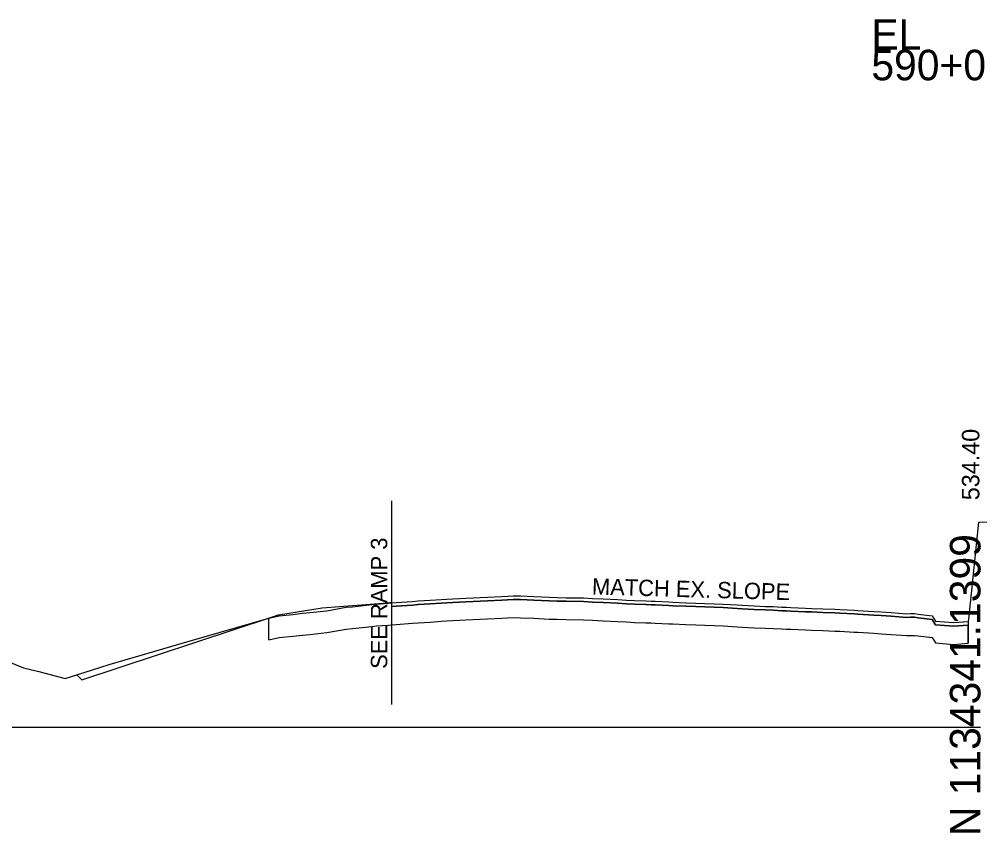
# Model space of a CAD drawing. Extents: x -201 to 2007062, y -213 to 1139737.
# Drawn here: x 1161.9 to 1249.9, y 3990.3 to 4064.9 of the extents above; entities that cross this region are included whole.
import ezdxf

# ---------------------------------------------------------------- set-up
doc = ezdxf.new("R2010")
doc.units = 0
for name, color, linetype in [('RD_DTM_Design_FG', 7, 'Continuous'), ('RD_GPK_XS_Cell', 7, 'Continuous'), ('RD_XS_ExGround', 7, 'Continuous'), ('RD_XS_ExPaveRet', 7, 'Continuous'), ('RD_XS_PaveOvlay', 7, 'Continuous'), ('RD_XS_SideStreet', 7, 'Continuous'), ('RD_XS_TX_Elev_EX', 7, 'Continuous'), ('RD_XS_TX_Slope', 7, 'Continuous')]:
    doc.layers.add(name, color=color, linetype=linetype)

msp = doc.modelspace()

# ---------------------------------------------------------------- linework, layer by layer
at = {"layer": 'RD_DTM_Design_FG'}
msp.add_lwpolyline([(1167.175, 4004.78), (1167.636, 4004.319), (1185.029, 4010.089), (1185.65, 4010.295), (1189.653, 4010.93), (1195.658, 4011.402), (1195.828, 4011.409), (1196, 4011.416)], dxfattribs=at)
at = {"layer": 'RD_GPK_XS_Cell'}
msp.add_line((1000, 4000), (1250, 4000), dxfattribs=at)
at = {"layer": 'RD_XS_ExGround'}
msp.add_lwpolyline([(1141.212, 4014.029), (1162.282, 4005.435), (1163.673, 4005.085), (1166.114, 4004.438), (1168.61, 4005.245), (1170.121, 4005.742), (1177.268, 4007.819), (1184.759, 4009.984), (1185.728, 4010.204), (1186.963, 4010.336), (1187.85, 4010.431), (1188.53, 4010.498), (1190.097, 4010.669), (1191.874, 4010.985), (1192.441, 4011.038), (1194.214, 4011.225), (1194.653, 4011.275), (1195.733, 4011.357), (1196.448, 4011.408), (1197.932, 4011.52), (1198.457, 4011.56), (1199.557, 4011.633), (1200.579, 4011.7), (1201.066, 4011.732), (1202.84, 4011.825), (1204.822, 4011.912), (1206.123, 4011.981), (1207.181, 4012.032), (1207.825, 4012.018), (1209.065, 4011.97), (1210.469, 4011.906), (1211.186, 4011.883), (1212.036, 4011.864), (1213.603, 4011.84), (1214.439, 4011.797), (1215.429, 4011.747), (1216.737, 4011.692), (1217.55, 4011.638), (1218.304, 4011.594), (1219.329, 4011.561), (1219.823, 4011.544), (1220.182, 4011.533), (1221.438, 4011.477), (1221.793, 4011.457), (1223.006, 4011.403), (1223.915, 4011.374), (1226.432, 4011.281), (1227.707, 4011.204), (1228.158, 4011.171), (1229.274, 4011.111), (1230.279, 4011.069), (1230.991, 4011.04), (1231.788, 4010.992), (1232.186, 4010.984), (1232.61, 4010.964), (1233.975, 4010.91), (1234.522, 4010.885), (1235.542, 4010.839), (1236.644, 4010.804), (1237.109, 4010.784), (1238.426, 4010.713), (1238.765, 4010.695), (1240.243, 4010.606), (1240.886, 4010.559), (1241.811, 4010.5), (1243.209, 4010.394), (1243.596, 4010.405), (1243.947, 4010.4), (1244.298, 4010.355), (1245.59, 4010.203), (1245.875, 4009.714), (1247.518, 4009.575), (1248.91, 4009.685), (1248.959, 4010.155), (1249.867, 4018.796), (1250.638, 4018.815)], dxfattribs=at)
at = {"layer": 'RD_XS_ExPaveRet'}
for p, q in [((1196, 4011.043), (1196, 4009.376)), ((1184.758, 4007.984), (1184.758, 4009.984)), ((1202.84, 4009.825), (1204.822, 4009.912)), ((1202.84, 4009.825), (1204.822, 4009.912)), ((1204.822, 4009.912), (1206.123, 4009.981)), ((1204.822, 4009.912), (1206.123, 4009.981)), ((1206.123, 4009.981), (1207.181, 4010.032)), ((1206.123, 4009.981), (1207.181, 4010.032)), ((1207.181, 4010.032), (1207.825, 4010.018)), ((1207.181, 4010.032), (1207.825, 4010.018)), ((1207.825, 4010.018), (1209.065, 4009.97)), ((1207.825, 4010.018), (1209.065, 4009.97)), ((1209.065, 4009.97), (1210.469, 4009.906)), ((1209.065, 4009.97), (1210.469, 4009.906)), ((1210.469, 4009.906), (1211.186, 4009.883)), ((1210.469, 4009.906), (1211.186, 4009.883)), ((1211.186, 4009.883), (1212.036, 4009.864)), ((1211.186, 4009.883), (1212.036, 4009.864)), ((1212.036, 4009.864), (1213.603, 4009.84)), ((1212.036, 4009.864), (1213.603, 4009.84)), ((1190.097, 4008.669), (1191.874, 4008.985)), ((1191.874, 4008.985), (1192.441, 4009.038)), ((1192.441, 4009.038), (1194.214, 4009.225)), ((1194.214, 4009.225), (1194.653, 4009.275)), ((1194.653, 4009.275), (1195.733, 4009.357)), ((1195.733, 4009.357), (1196.448, 4009.408)), ((1196, 4009.376), (1196.448, 4009.408)), ((1196.448, 4009.408), (1197.932, 4009.52)), ((1196.448, 4009.408), (1197.932, 4009.52)), ((1197.932, 4009.52), (1198.457, 4009.56)), ((1197.932, 4009.52), (1198.457, 4009.56)), ((1198.457, 4009.56), (1199.557, 4009.633)), ((1198.457, 4009.56), (1199.557, 4009.633)), ((1199.557, 4009.633), (1200.579, 4009.7)), ((1199.557, 4009.633), (1200.579, 4009.7)), ((1200.579, 4009.7), (1201.066, 4009.732)), ((1200.579, 4009.7), (1201.066, 4009.732)), ((1201.066, 4009.732), (1202.84, 4009.825)), ((1201.066, 4009.732), (1202.84, 4009.825)), ((1213.603, 4009.84), (1214.439, 4009.797)), ((1213.603, 4009.84), (1214.439, 4009.797)), ((1214.439, 4009.797), (1215.429, 4009.747)), ((1214.439, 4009.797), (1215.429, 4009.747)), ((1215.429, 4009.747), (1216.737, 4009.692)), ((1215.429, 4009.747), (1216.737, 4009.692)), ((1216.737, 4009.692), (1217.55, 4009.638)), ((1216.737, 4009.692), (1217.55, 4009.638)), ((1217.55, 4009.638), (1218.304, 4009.594)), ((1217.55, 4009.638), (1218.304, 4009.594)), ((1218.304, 4009.594), (1219.329, 4009.561)), ((1218.304, 4009.594), (1219.329, 4009.561)), ((1219.329, 4009.561), (1219.823, 4009.544)), ((1219.329, 4009.561), (1219.823, 4009.544)), ((1219.823, 4009.544), (1220.182, 4009.533)), ((1219.823, 4009.544), (1220.182, 4009.533)), ((1220.182, 4009.533), (1221.438, 4009.477)), ((1220.182, 4009.533), (1221.438, 4009.477)), ((1221.438, 4009.477), (1221.793, 4009.457)), ((1221.438, 4009.477), (1221.793, 4009.457)), ((1221.793, 4009.457), (1223.006, 4009.403)), ((1221.793, 4009.457), (1223.006, 4009.403)), ((1223.006, 4009.403), (1223.915, 4009.374)), ((1223.006, 4009.403), (1223.915, 4009.374)), ((1223.915, 4009.374), (1226.432, 4009.281)), ((1223.915, 4009.374), (1226.432, 4009.281)), ((1226.432, 4009.281), (1227.707, 4009.204)), ((1226.432, 4009.281), (1227.707, 4009.204)), ((1227.707, 4009.204), (1228.158, 4009.171)), ((1227.707, 4009.204), (1228.158, 4009.171)), ((1228.158, 4009.171), (1229.274, 4009.111)), ((1228.158, 4009.171), (1229.274, 4009.111)), ((1229.274, 4009.111), (1230.279, 4009.069)), ((1229.274, 4009.111), (1230.279, 4009.069)), ((1230.279, 4009.069), (1230.991, 4009.04)), ((1230.279, 4009.069), (1230.991, 4009.04)), ((1230.991, 4009.04), (1231.788, 4008.992)), ((1230.991, 4009.04), (1231.788, 4008.992)), ((1231.788, 4008.992), (1232.186, 4008.984)), ((1231.788, 4008.992), (1232.186, 4008.984)), ((1232.186, 4008.984), (1232.61, 4008.964)), ((1232.186, 4008.984), (1232.61, 4008.964)), ((1248.885, 4009.683), (1248.885, 4007.683)), ((1248.885, 4007.683), (1248.885, 4009.35)), ((1184.759, 4007.984), (1185.728, 4008.204)), ((1185.728, 4008.204), (1186.963, 4008.336)), ((1186.963, 4008.336), (1187.85, 4008.431)), ((1187.85, 4008.431), (1188.53, 4008.498)), ((1188.53, 4008.498), (1190.097, 4008.669)), ((1232.61, 4008.964), (1233.975, 4008.91)), ((1232.61, 4008.964), (1233.975, 4008.91)), ((1233.975, 4008.91), (1234.522, 4008.885)), ((1233.975, 4008.91), (1234.522, 4008.885)), ((1234.522, 4008.885), (1235.542, 4008.839)), ((1234.522, 4008.885), (1235.542, 4008.839)), ((1235.542, 4008.839), (1236.644, 4008.804)), ((1235.542, 4008.839), (1236.644, 4008.804)), ((1236.644, 4008.804), (1237.109, 4008.784)), ((1236.644, 4008.804), (1237.109, 4008.784)), ((1237.109, 4008.784), (1238.426, 4008.713)), ((1237.109, 4008.784), (1238.426, 4008.713)), ((1238.426, 4008.713), (1238.765, 4008.695)), ((1238.426, 4008.713), (1238.765, 4008.695)), ((1238.765, 4008.695), (1240.243, 4008.606)), ((1238.765, 4008.695), (1240.243, 4008.606)), ((1240.243, 4008.606), (1240.886, 4008.559)), ((1240.243, 4008.606), (1240.886, 4008.559)), ((1240.886, 4008.559), (1241.811, 4008.5)), ((1240.886, 4008.559), (1241.811, 4008.5)), ((1241.811, 4008.5), (1243.209, 4008.394)), ((1241.811, 4008.5), (1243.209, 4008.394)), ((1243.209, 4008.394), (1243.596, 4008.405)), ((1243.209, 4008.394), (1243.596, 4008.405)), ((1243.596, 4008.405), (1243.947, 4008.4)), ((1243.596, 4008.405), (1243.947, 4008.4)), ((1243.947, 4008.4), (1244.298, 4008.355)), ((1243.947, 4008.4), (1244.298, 4008.355)), ((1244.298, 4008.355), (1245.59, 4008.203)), ((1244.298, 4008.355), (1245.59, 4008.203)), ((1245.59, 4008.203), (1245.875, 4007.714)), ((1245.59, 4008.203), (1245.875, 4007.714)), ((1184.758, 4007.984), (1184.759, 4007.984)), ((1245.875, 4007.714), (1247.518, 4007.575)), ((1245.875, 4007.714), (1247.518, 4007.575)), ((1247.518, 4007.575), (1248.885, 4007.683)), ((1247.518, 4007.575), (1248.885, 4007.683))]:
    msp.add_line(p, q, dxfattribs=at)
msp.add_lwpolyline([(1248.885, 4009.35), (1247.518, 4009.242), (1245.875, 4009.381), (1245.59, 4009.87), (1244.298, 4010.022), (1243.947, 4010.067), (1243.596, 4010.072), (1243.209, 4010.061), (1241.811, 4010.167), (1240.886, 4010.226), (1240.243, 4010.273), (1238.765, 4010.362), (1238.426, 4010.38), (1237.109, 4010.451), (1236.644, 4010.471), (1235.542, 4010.506), (1234.522, 4010.552), (1233.975, 4010.577), (1232.61, 4010.631), (1232.186, 4010.651), (1231.788, 4010.659), (1230.991, 4010.707), (1230.279, 4010.736), (1229.274, 4010.778), (1228.158, 4010.838), (1227.707, 4010.871), (1226.432, 4010.948), (1223.915, 4011.041), (1223.006, 4011.07), (1221.793, 4011.124), (1221.438, 4011.144), (1220.182, 4011.2), (1219.823, 4011.211), (1219.329, 4011.228), (1218.304, 4011.261), (1217.55, 4011.305), (1216.737, 4011.359), (1215.429, 4011.414), (1214.439, 4011.464), (1213.603, 4011.507), (1212.036, 4011.531), (1211.186, 4011.55), (1210.469, 4011.573), (1209.065, 4011.637), (1207.825, 4011.685), (1207.181, 4011.699), (1206.123, 4011.648), (1204.822, 4011.579), (1202.84, 4011.492), (1201.066, 4011.399), (1200.579, 4011.367), (1199.557, 4011.3), (1198.457, 4011.227), (1197.932, 4011.187), (1196.448, 4011.075), (1196, 4011.043)], dxfattribs=at)
at = {"layer": 'RD_XS_PaveOvlay'}
msp.add_line((1196, 4011.376), (1196, 4011.043), dxfattribs=at)
for points in [[(1196, 4011.376), (1196.448, 4011.408), (1197.932, 4011.52), (1198.457, 4011.56), (1199.557, 4011.633), (1200.579, 4011.7), (1201.066, 4011.732), (1202.84, 4011.825), (1204.822, 4011.912), (1206.123, 4011.981), (1207.181, 4012.032), (1207.825, 4012.018), (1209.065, 4011.97), (1210.469, 4011.906), (1211.186, 4011.883), (1212.036, 4011.864), (1213.603, 4011.84), (1214.439, 4011.797), (1215.429, 4011.747), (1216.737, 4011.692), (1217.55, 4011.638), (1218.304, 4011.594), (1219.329, 4011.561), (1219.823, 4011.544), (1220.182, 4011.533), (1221.438, 4011.477), (1221.793, 4011.457), (1223.006, 4011.403), (1223.915, 4011.374), (1226.432, 4011.281), (1227.707, 4011.204), (1228.158, 4011.171), (1229.274, 4011.111), (1230.279, 4011.069), (1230.991, 4011.04), (1231.788, 4010.992), (1232.186, 4010.984), (1232.61, 4010.964), (1233.975, 4010.91), (1234.522, 4010.885), (1235.542, 4010.839), (1236.644, 4010.804), (1237.109, 4010.784), (1238.426, 4010.713), (1238.765, 4010.695), (1240.243, 4010.606), (1240.886, 4010.559), (1241.811, 4010.5), (1243.209, 4010.394), (1243.596, 4010.405), (1243.947, 4010.4), (1244.298, 4010.355), (1245.59, 4010.203), (1245.875, 4009.714), (1247.518, 4009.575), (1248.885, 4009.683)], [(1196, 4011.043), (1196.448, 4011.075), (1197.932, 4011.187), (1198.457, 4011.227), (1199.557, 4011.3), (1200.579, 4011.367), (1201.066, 4011.399), (1202.84, 4011.492), (1204.822, 4011.579), (1206.123, 4011.648), (1207.181, 4011.699), (1207.825, 4011.685), (1209.065, 4011.637), (1210.469, 4011.573), (1211.186, 4011.55), (1212.036, 4011.531), (1213.603, 4011.507), (1214.439, 4011.464), (1215.429, 4011.414), (1216.737, 4011.359), (1217.55, 4011.305), (1218.304, 4011.261), (1219.329, 4011.228), (1219.823, 4011.211), (1220.182, 4011.2), (1221.438, 4011.144), (1221.793, 4011.124), (1223.006, 4011.07), (1223.915, 4011.041), (1226.432, 4010.948), (1227.707, 4010.871), (1228.158, 4010.838), (1229.274, 4010.778), (1230.279, 4010.736), (1230.991, 4010.707), (1231.788, 4010.659), (1232.186, 4010.651), (1232.61, 4010.631), (1233.975, 4010.577), (1234.522, 4010.552), (1235.542, 4010.506), (1236.644, 4010.471), (1237.109, 4010.451), (1238.426, 4010.38), (1238.765, 4010.362), (1240.243, 4010.273), (1240.886, 4010.226), (1241.811, 4010.167), (1243.209, 4010.061), (1243.596, 4010.072), (1243.947, 4010.067), (1244.298, 4010.022), (1245.59, 4009.87), (1245.875, 4009.381), (1247.518, 4009.242), (1248.885, 4009.35)]]:
    msp.add_lwpolyline(points, dxfattribs=at)
at = {"layer": 'RD_XS_SideStreet'}
msp.add_line((1196, 4020.746), (1196, 4002.067), dxfattribs=at)

# ---------------------------------------------------------------- texts
at = {"layer": 'RD_GPK_XS_Cell'}
for s, p in [('EL', (1240, 4062.099)), ('590+00.00 / 1', (1240, 4059.299))]:
    msp.add_text(s, height=2.8, dxfattribs=at).set_placement(p)
msp.add_text('N 1134341.1399', height=2.8, rotation=90, dxfattribs=at).set_placement((1250, 3990))
at = {"layer": 'RD_XS_SideStreet'}
msp.add_text('SEE RAMP 3', height=1.5, rotation=90, dxfattribs=at).set_placement((1195.623, 4005.335))
at = {"layer": 'RD_XS_TX_Elev_EX'}
msp.add_text('534.40', height=1.6, rotation=90, dxfattribs=at).set_placement((1249.9, 4020.799))
at = {"layer": 'RD_XS_TX_Slope'}
msp.add_text('MATCH EX. SLOPE', height=1.5, rotation=358.36707, dxfattribs=at).set_placement((1214.375, 4012.154))

doc.saveas('drawing.dxf')
